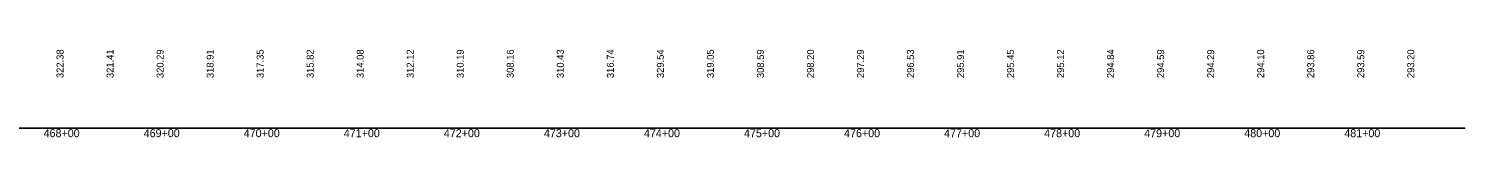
# Model space of a CAD drawing. Extents: x 1876258 to 1926563, y 729739 to 834437.
# Drawn here: x 1925127 to 1926563, y 830495 to 830583 of the extents above; entities that cross this region are included whole.
import ezdxf

# ---------------------------------------------------------------- set-up
doc = ezdxf.new("R2010")
doc.units = 0
for name, color, linetype in [('RD_EX_RailRoad', 7, 'Continuous'), ('RD_PD_ALT3_CL', 7, 'Continuous'), ('RD_PD_Final_Cl', 7, 'Continuous')]:
    doc.layers.add(name, color=color, linetype=linetype)

msp = doc.modelspace()

# ---------------------------------------------------------------- linework, layer by layer
at = {"layer": 'RD_PD_Final_Cl'}
msp.add_line((1878363.1, 830504.3), (1926563.1, 830504.3), dxfattribs=at)

# ---------------------------------------------------------------- texts
at = {"layer": 'RD_EX_RailRoad'}
for s, p in [('316.74', (1925712.1, 830554.3)), ('329.54', (1925762.1, 830554.3)), ('294.84', (1926212.1, 830554.3)), ('322.38', (1925162.1, 830554.3)), ('321.41', (1925212.1, 830554.3)), ('320.29', (1925262.1, 830554.3)), ('318.91', (1925312.1, 830554.3)), ('317.35', (1925362.1, 830554.3)), ('315.82', (1925412.1, 830554.3)), ('314.08', (1925462.1, 830554.3)), ('312.12', (1925512.1, 830554.3)), ('310.19', (1925562.1, 830554.3)), ('308.16', (1925612.1, 830554.3)), ('310.43', (1925662.1, 830554.3)), ('319.05', (1925812.1, 830554.3)), ('308.59', (1925862.1, 830554.3)), ('298.20', (1925912.1, 830554.3)), ('297.29', (1925962.1, 830554.3)), ('296.53', (1926012.1, 830554.3)), ('295.91', (1926062.1, 830554.3)), ('295.45', (1926112.1, 830554.3)), ('295.12', (1926162.1, 830554.3)), ('294.59', (1926262.1, 830554.3)), ('294.29', (1926312.1, 830554.3)), ('294.10', (1926362.1, 830554.3)), ('293.86', (1926412.1, 830554.3)), ('293.59', (1926462.1, 830554.3)), ('293.20', (1926512.1, 830554.3))]:
    msp.add_text(s, height=7, rotation=90, dxfattribs=at).set_placement(p)
at = {"layer": 'RD_PD_ALT3_CL'}
for s, p in [('468+00', (1925142.2, 830495.3)), ('468+00', (1925142.2, 830495.3)), ('469+00', (1925242.2, 830495.3)), ('469+00', (1925242.2, 830495.3)), ('470+00', (1925342.2, 830495.3)), ('470+00', (1925342.2, 830495.3)), ('471+00', (1925442.2, 830495.3)), ('471+00', (1925442.2, 830495.3)), ('472+00', (1925542.2, 830495.3)), ('472+00', (1925542.2, 830495.3)), ('473+00', (1925642.2, 830495.3)), ('473+00', (1925642.2, 830495.3)), ('474+00', (1925742.2, 830495.3)), ('474+00', (1925742.2, 830495.3)), ('475+00', (1925842.2, 830495.3)), ('475+00', (1925842.2, 830495.3)), ('476+00', (1925942.2, 830495.3)), ('476+00', (1925942.2, 830495.3)), ('477+00', (1926042.2, 830495.3)), ('477+00', (1926042.2, 830495.3)), ('478+00', (1926142.2, 830495.3)), ('478+00', (1926142.2, 830495.3)), ('479+00', (1926242.2, 830495.3)), ('479+00', (1926242.2, 830495.3)), ('480+00', (1926342.2, 830495.3)), ('480+00', (1926342.2, 830495.3)), ('481+00', (1926442.2, 830495.3)), ('481+00', (1926442.2, 830495.3))]:
    msp.add_text(s, height=8, dxfattribs=at).set_placement(p)

doc.saveas('drawing.dxf')
